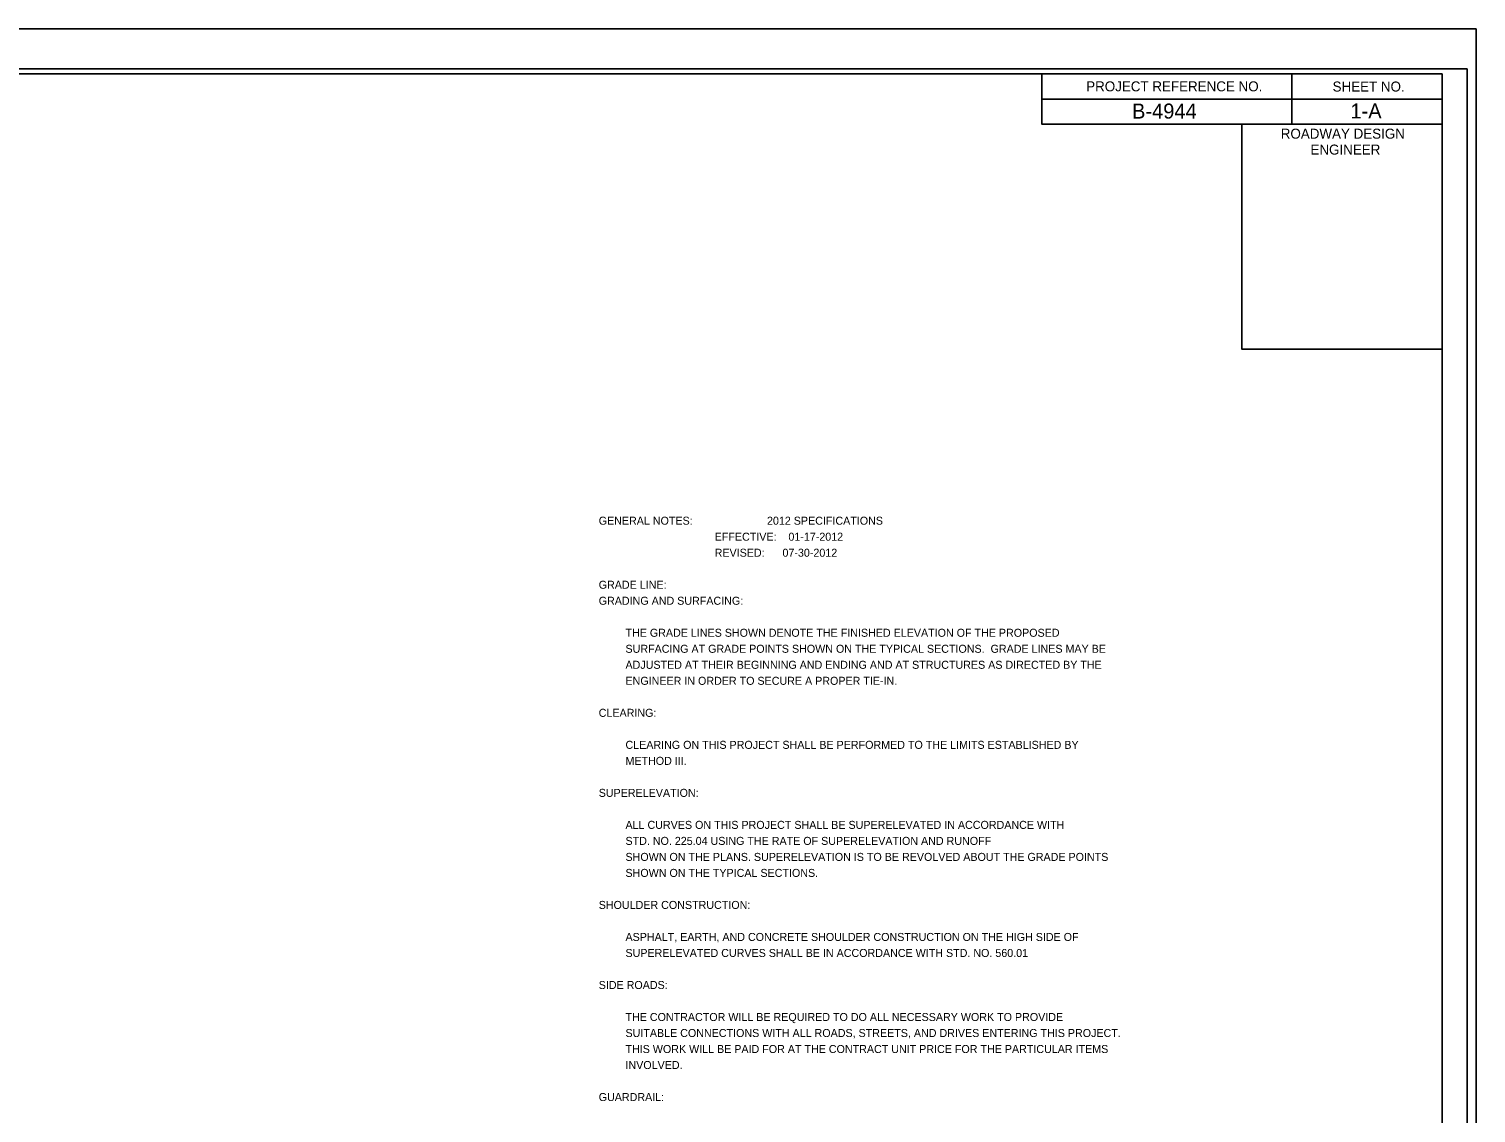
# Model space of a CAD drawing. Extents: x 573844.3 to 573878, y -53348.9 to -53327.
# Drawn here: x 573863.49 to 573877.96, y -53337.87 to -53327.03 of the extents above; entities that cross this region are included whole.
import ezdxf

# ---------------------------------------------------------------- set-up
doc = ezdxf.new("R2010")
doc.units = 0
for name, color, linetype in [('Default', 7, 'Continuous'), ('Sheet Cutting Line CELL', 7, 'Continuous'), ('Sheet Data Field CELL', 7, 'Continuous'), ('Sheet Plan CELL', 7, 'Continuous'), ('Sheet Plot Border Inside CELL', 7, 'Continuous'), ('Sheet Plot Border Outside CELL', 7, 'Continuous')]:
    doc.layers.add(name, color=color, linetype=linetype)

msp = doc.modelspace()

# ---------------------------------------------------------------- linework, layer by layer
at = {"layer": 'Sheet Cutting Line CELL'}
msp.add_line((573877.959, -53327.032), (573844.289, -53327.032), dxfattribs=at)
at = {"layer": 'Sheet Plan CELL'}
for p, q in [((573876.119, -53327.483), (573876.119, -53327.983)), ((573873.618, -53327.733), (573877.619, -53327.733)), ((573873.618, -53327.983), (573877.619, -53327.983)), ((573873.618, -53327.983), (573877.619, -53327.983)), ((573875.619, -53327.983), (573875.619, -53330.232))]:
    msp.add_line(p, q, dxfattribs=at)
for points in [[(573877.619, -53327.482), (573847.619, -53327.482), (573847.619, -53348.482), (573877.619, -53348.482)], [(573873.618, -53327.482), (573877.619, -53327.482), (573877.619, -53327.983), (573873.618, -53327.983)], [(573875.619, -53327.983), (573877.619, -53327.983), (573877.619, -53330.233), (573875.619, -53330.233)]]:
    msp.add_lwpolyline(points, close=True, dxfattribs=at)
at = {"layer": 'Sheet Plot Border Inside CELL'}
msp.add_lwpolyline([(573844.549, -53348.532), (573877.869, -53348.532), (573877.869, -53327.432), (573844.549, -53327.432)], close=True, dxfattribs=at)
at = {"layer": 'Sheet Plot Border Outside CELL'}
msp.add_lwpolyline([(573844.289, -53348.932), (573877.959, -53348.932), (573877.959, -53327.032), (573844.289, -53327.032)], close=True, dxfattribs=at)

# ---------------------------------------------------------------- texts
at = {"layer": 'Default'}
for s, p in [('GENERAL NOTES:                         2012 SPECIFICATIONS', (573869.189, -53331.987)), ('                                       EFFECTIVE:    01-17-2012', (573869.189, -53332.147)), ('                                       REVISED:      07-30-2012', (573869.189, -53332.307)), ('GRADE LINE:  ', (573869.189, -53332.627)), ('GRADING AND SURFACING:  ', (573869.189, -53332.787)), ('         THE GRADE LINES SHOWN DENOTE THE FINISHED ELEVATION OF THE PROPOSED ', (573869.189, -53333.107)), ('         SURFACING AT GRADE POINTS SHOWN ON THE TYPICAL SECTIONS.  GRADE LINES MAY BE ', (573869.189, -53333.267)), ('         ADJUSTED AT THEIR BEGINNING AND ENDING AND AT STRUCTURES AS DIRECTED BY THE ', (573869.189, -53333.427)), ('         ENGINEER IN ORDER TO SECURE A PROPER TIE-IN.  ', (573869.189, -53333.587)), ('CLEARING:  ', (573869.189, -53333.907)), ('         CLEARING ON THIS PROJECT SHALL BE PERFORMED TO THE LIMITS ESTABLISHED BY ', (573869.189, -53334.227)), ('         METHOD III.', (573869.189, -53334.387)), ('SUPERELEVATION:  ', (573869.189, -53334.707)), ('         ALL CURVES ON THIS PROJECT SHALL BE SUPERELEVATED IN ACCORDANCE WITH', (573869.189, -53335.027)), ('         STD. NO. 225.04 USING THE RATE OF SUPERELEVATION AND RUNOFF ', (573869.189, -53335.187)), ('         SHOWN ON THE PLANS. SUPERELEVATION IS TO BE REVOLVED ABOUT THE GRADE POINTS ', (573869.189, -53335.347)), ('         SHOWN ON THE TYPICAL SECTIONS.  ', (573869.189, -53335.507)), ('SHOULDER CONSTRUCTION:  ', (573869.189, -53335.827)), ('         ASPHALT, EARTH, AND CONCRETE SHOULDER CONSTRUCTION ON THE HIGH SIDE OF', (573869.189, -53336.147)), ('         SUPERELEVATED CURVES SHALL BE IN ACCORDANCE WITH STD. NO. 560.01 ', (573869.189, -53336.307)), ('SIDE ROADS:  ', (573869.189, -53336.627)), ('         THE CONTRACTOR WILL BE REQUIRED TO DO ALL NECESSARY WORK TO PROVIDE ', (573869.189, -53336.947)), ('         SUITABLE CONNECTIONS WITH ALL ROADS, STREETS, AND DRIVES ENTERING THIS PROJECT.  ', (573869.189, -53337.107)), ('         THIS WORK WILL BE PAID FOR AT THE CONTRACT UNIT PRICE FOR THE PARTICULAR ITEMS ', (573869.189, -53337.267)), ('         INVOLVED.  ', (573869.189, -53337.427)), ('GUARDRAIL:  ', (573869.189, -53337.747))]:
    msp.add_text(s, height=0.08, dxfattribs=at).set_placement(p)
at = {"layer": 'Sheet Data Field CELL'}
for s, p in [('B-4944', (573874.52, -53327.928)), ('1-A', (573876.703, -53327.927))]:
    msp.add_text(s, height=0.15, dxfattribs=at).set_placement(p)
at = {"layer": 'Sheet Plan CELL'}
for s, p in [('PROJECT REFERENCE NO.', (573874.062, -53327.656)), ('SHEET NO.', (573876.525, -53327.658)), ('ROADWAY DESIGN', (573876.007, -53328.129)), ('ENGINEER', (573876.304, -53328.288))]:
    msp.add_text(s, height=0.1, dxfattribs=at).set_placement(p)

doc.saveas('drawing.dxf')
